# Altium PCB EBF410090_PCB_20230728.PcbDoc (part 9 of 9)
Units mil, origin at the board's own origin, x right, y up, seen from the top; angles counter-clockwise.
Board outline 5393.69 x 3858.26 mil, 6 copper layers (TOP, GND02, ART03, ART04, PWR05, BOTTOM), stack 47.2 mil thick; 570 components, 437 nets, 2015 pads, 1260 vias.
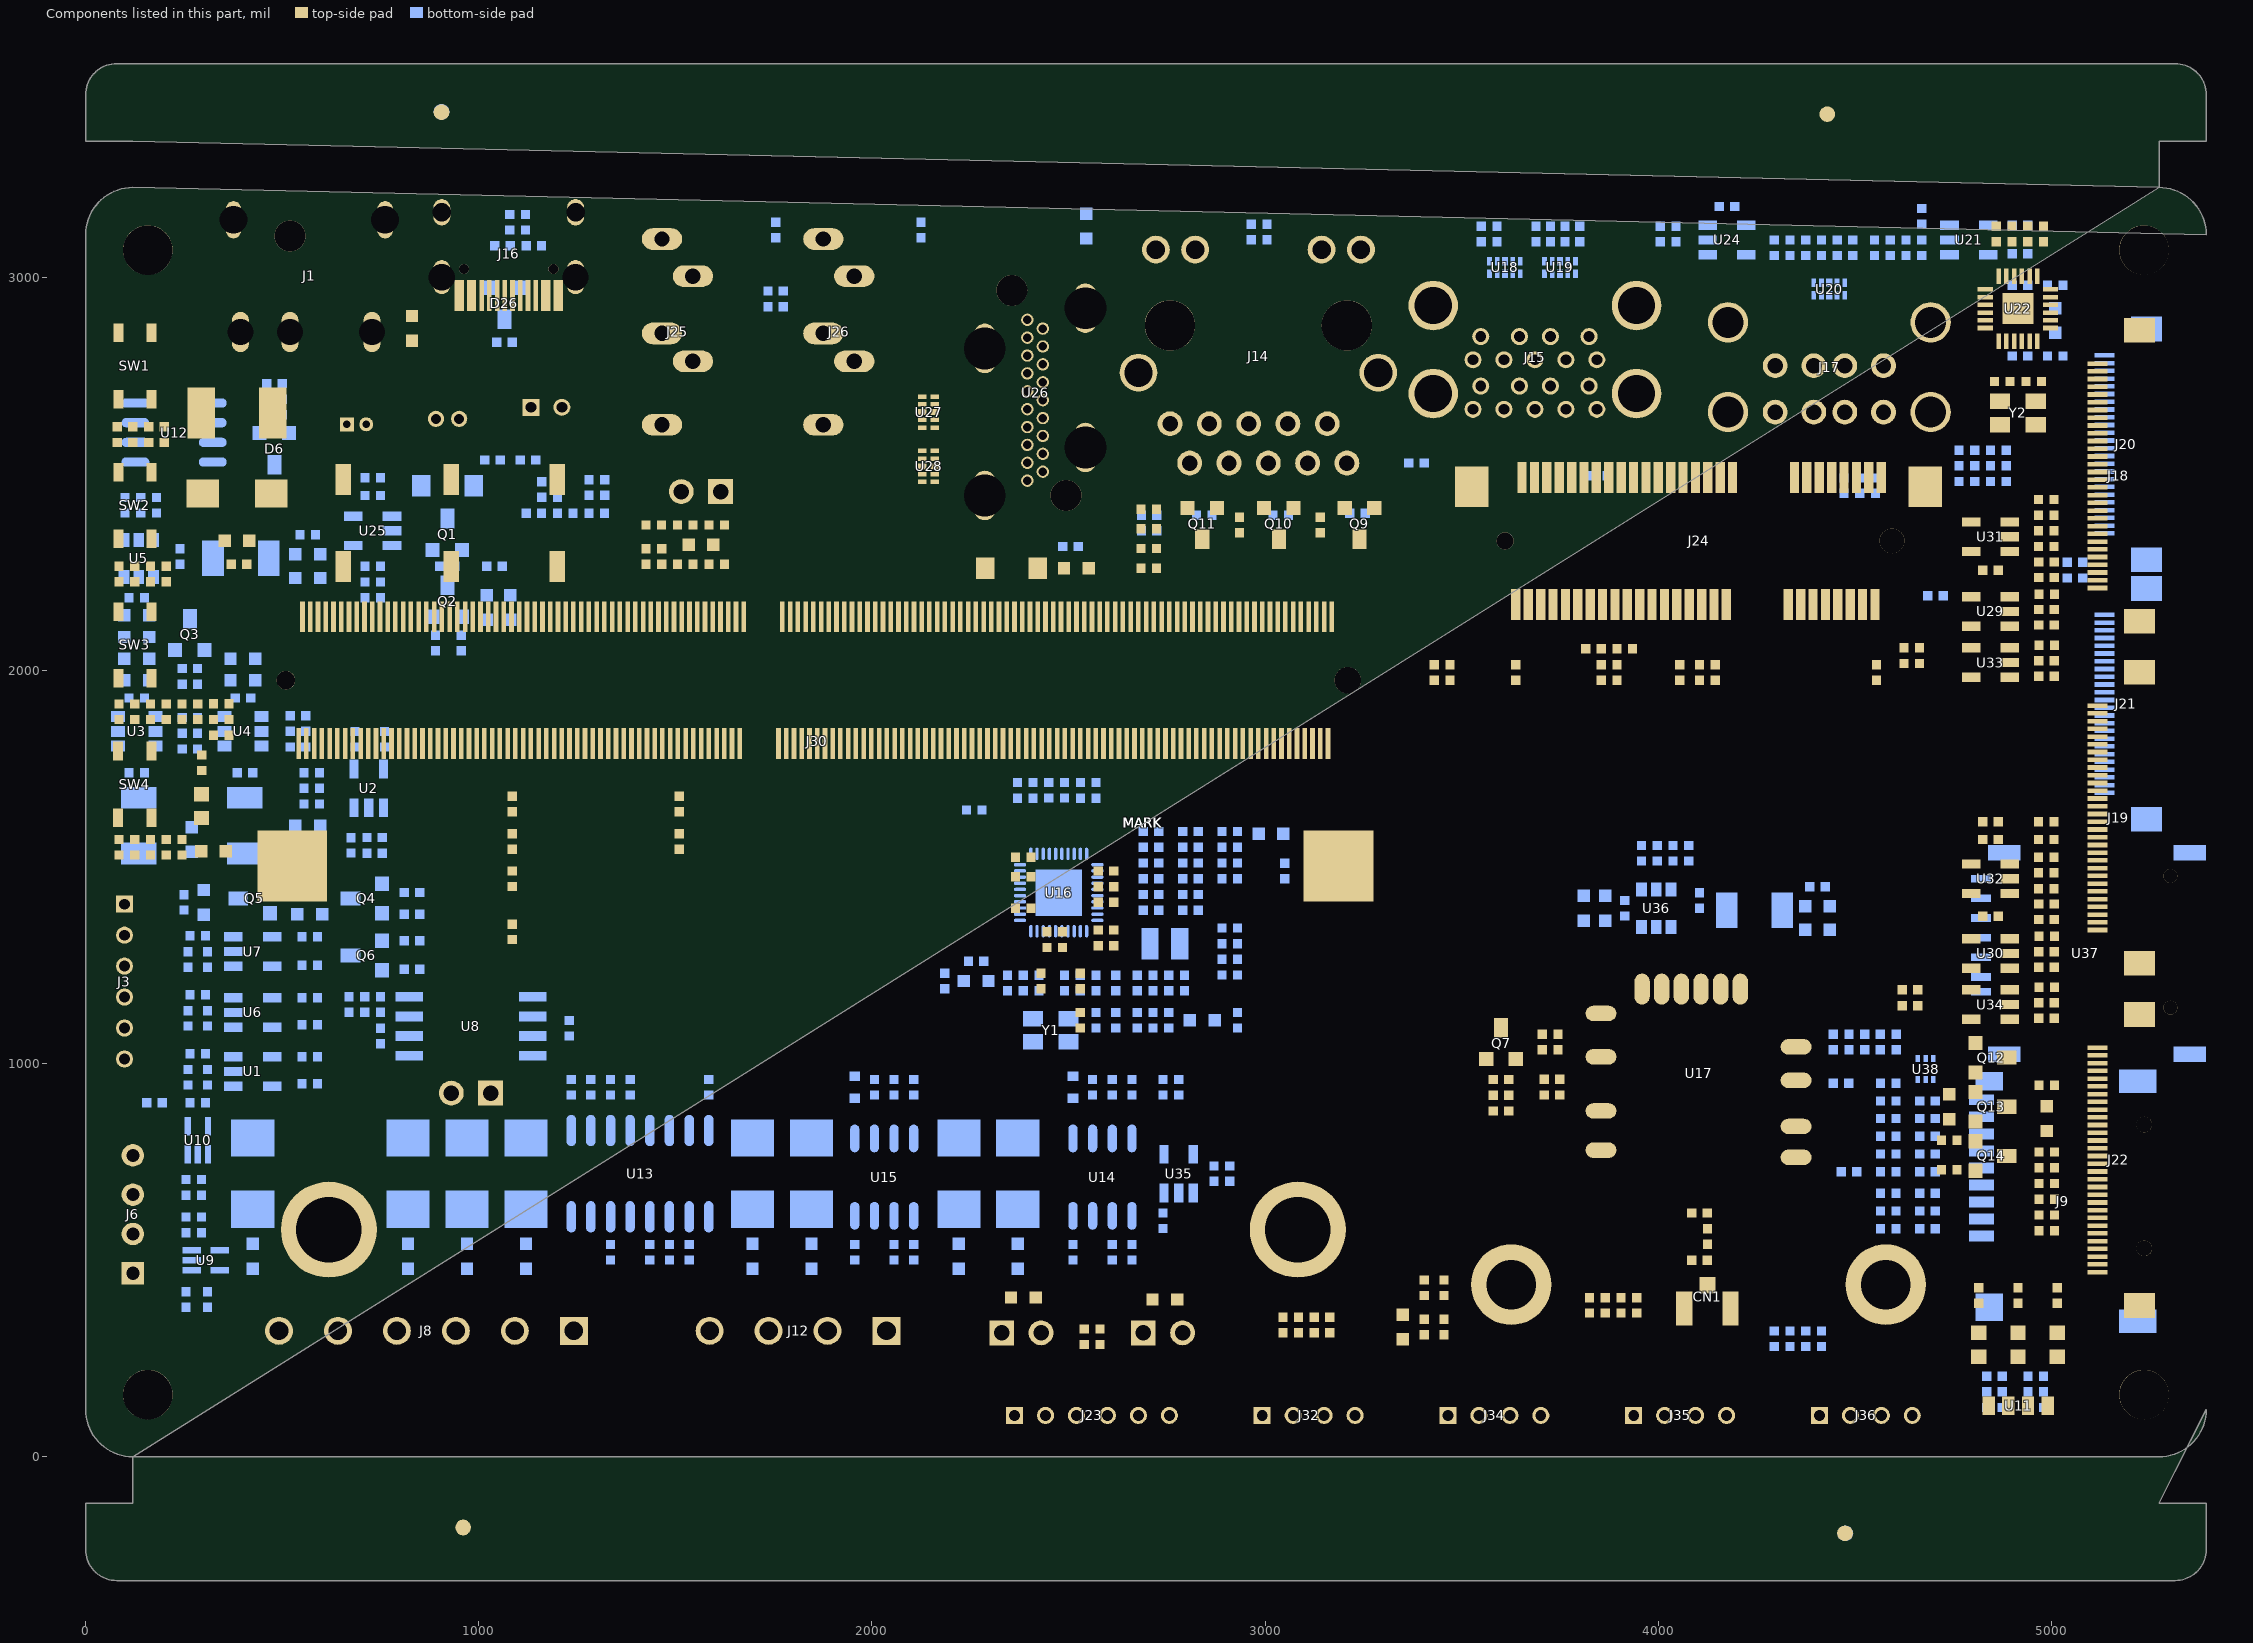
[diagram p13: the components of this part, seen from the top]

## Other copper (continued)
BOTTOM:
  region net GND: 896.3,2616 905.6,2625.33 890.99,2641.8 876.38,2625.33 885.68,2616 886.16,2615.56 886.68,2615.16 887.23,2614.81 887.81,2614.51 888.42,2614.25 889.04,2614.06 889.68,2613.92 890.33,2613.83 890.98,2613.8 891.64,2613.83 892.29,2613.91 892.92,2614.05 893.55,2614.25 894.15,2614.5 894.73,2614.8 895.29,2615.15 895.81,2615.55 896.29,2615.99 896.3,2616
  region net B_DP2: 4424.11,2806.64 4395.73,2806.64 4395.18,2774.6 4427.22,2775.15 4427.22,2803.53 4427.21,2803.8 4427.17,2804.07 4427.11,2804.33 4427.03,2804.59 4426.93,2804.84 4426.8,2805.09 4426.66,2805.31 4426.49,2805.53 4426.31,2805.73 4426.11,2805.91 4425.89,2806.08 4425.66,2806.22 4425.42,2806.35 4425.17,2806.45 4424.91,2806.53 4424.65,2806.59 4424.38,2806.63 4424.11,2806.64
  region net N15603170: 3245.6,2534.59 3230.39,2549.78 3205.63,2527.52 3230.39,2505.26 3245.6,2520.45 3246.19,2521.09 3246.72,2521.78 3247.19,2522.52 3247.59,2523.29 3247.93,2524.1 3248.19,2524.93 3248.38,2525.78 3248.49,2526.65 3248.53,2527.52 3248.49,2528.39 3248.38,2529.26 3248.19,2530.11 3247.93,2530.94 3247.59,2531.75 3247.19,2532.52 3246.72,2533.26 3246.19,2533.95 3245.6,2534.59
  region net VCC5V0_USB20_HOST: 4565.83,2812.62 4550.64,2797.41 4572.9,2772.65 4595.16,2797.41 4579.97,2812.62 4579.33,2813.21 4578.64,2813.74 4577.9,2814.21 4577.13,2814.61 4576.32,2814.95 4575.49,2815.21 4574.64,2815.4 4573.77,2815.51 4572.9,2815.55 4572.03,2815.51 4571.16,2815.4 4570.31,2815.21 4569.48,2814.95 4568.67,2814.61 4567.9,2814.21 4567.16,2813.74 4566.47,2813.21 4565.83,2812.62
  region net EDP_TP_RESET: 2538.78,126.66 2520.2,126.65 2519.66,104.47 2541.85,105.01 2541.86,123.58 2541.85,123.85 2541.81,124.11 2541.76,124.38 2541.67,124.63 2541.57,124.88 2541.45,125.12 2541.3,125.35 2541.14,125.56 2540.96,125.76 2540.76,125.94 2540.55,126.1 2540.32,126.25 2540.08,126.37 2539.83,126.47 2539.58,126.56 2539.31,126.61 2539.05,126.65 2538.78,126.66
  region net N18341998: 3100.72,3063.37 3118.7,3045.39 3146.26,3070.44 3118.7,3095.49 3100.72,3077.51 3100.13,3076.87 3099.6,3076.18 3099.13,3075.44 3098.73,3074.67 3098.39,3073.86 3098.13,3073.03 3097.94,3072.18 3097.83,3071.31 3097.79,3070.44 3097.83,3069.57 3097.94,3068.7 3098.13,3067.85 3098.39,3067.02 3098.73,3066.21 3099.13,3065.44 3099.6,3064.7 3100.13,3064.01 3100.72,3063.37
  region net VCC5V0_USB20_HOST: 4579.97,2737.68 4595.16,2752.89 4572.9,2777.65 4550.64,2752.89 4565.83,2737.68 4566.47,2737.09 4567.16,2736.56 4567.9,2736.09 4568.67,2735.69 4569.48,2735.35 4570.31,2735.09 4571.16,2734.9 4572.03,2734.79 4572.9,2734.75 4573.77,2734.79 4574.64,2734.9 4575.49,2735.09 4576.32,2735.35 4577.13,2735.69 4577.9,2736.09 4578.64,2736.56 4579.33,2737.09 4579.97,2737.68
  region net N15852295: 1167.28,2648.57 1154.14,2690.94 1131.47,2670.02 1110.82,2647.64 1162.37,2642.64 1162.81,2642.66 1163.24,2642.72 1163.66,2642.81 1164.08,2642.94 1164.48,2643.11 1164.87,2643.31 1165.24,2643.54 1165.58,2643.81 1165.91,2644.1 1166.2,2644.43 1166.47,2644.77 1166.7,2645.14 1166.9,2645.53 1167.07,2645.93 1167.2,2646.35 1167.29,2646.77 1167.35,2647.2 1167.37,2647.64 1167.35,2648.08 1167.29,2648.51 1167.28,2648.57
  region net N17975561: 661.06,2660.41 646.66,2643.7 664.37,2624.48 682.08,2643.7 667.68,2660.41 667.23,2660.68 666.76,2660.9 666.27,2661.09 665.77,2661.24 665.25,2661.33 664.73,2661.39 664.21,2661.4 663.69,2661.36 663.17,2661.28 662.66,2661.15 662.17,2660.98 661.69,2660.77 661.23,2660.51 661.06,2660.41
  region net EDP_TP_INT: 2460.04,126.66 2441.46,126.65 2440.92,104.47 2463.11,105.01 2463.12,123.58 2463.11,123.85 2463.07,124.11 2463.02,124.38 2462.93,124.63 2462.83,124.88 2462.71,125.12 2462.56,125.35 2462.4,125.56 2462.22,125.76 2462.02,125.94 2461.81,126.1 2461.58,126.25 2461.34,126.37 2461.09,126.47 2460.84,126.56 2460.57,126.61 2460.31,126.65 2460.04,126.66
  region net B_DP3: 4424.11,2688.54 4395.73,2688.52 4395.18,2656.49 4427.22,2657.04 4427.22,2685.42 4427.21,2685.69 4427.17,2685.96 4427.11,2686.23 4427.03,2686.49 4426.93,2686.74 4426.8,2686.98 4426.66,2687.21 4426.49,2687.43 4426.31,2687.63 4426.11,2687.81 4425.89,2687.98 4425.66,2688.12 4425.42,2688.25 4425.17,2688.35 4424.91,2688.43 4424.64,2688.49 4424.37,2688.53 4424.11,2688.54
  region net N17702199: 1633.51,323.71 1611.98,345.22 1585.68,320.17 1611.98,295.12 1633.51,316.63 1633.81,316.95 1634.07,317.3 1634.31,317.67 1634.51,318.05 1634.68,318.46 1634.81,318.87 1634.9,319.3 1634.96,319.73 1634.98,320.17 1634.96,320.61 1634.9,321.04 1634.81,321.47 1634.68,321.88 1634.51,322.29 1634.31,322.68 1634.07,323.04 1633.81,323.39 1633.51,323.71
  region net N18495175: 4486.52,133.46 4473.4,120.32 4488.7,104.24 4504,120.32 4490.88,133.46 4490.68,133.64 4490.47,133.8 4490.24,133.95 4490,134.07 4489.75,134.17 4489.5,134.26 4489.23,134.31 4488.97,134.35 4488.7,134.36 4488.43,134.35 4488.17,134.31 4487.9,134.26 4487.65,134.17 4487.4,134.07 4487.16,133.95 4486.93,133.8 4486.72,133.64 4486.52,133.46
  region net N17731599: 456.23,350.6 456.24,320.17 492.54,319.29 491.66,355.59 461.23,355.6 460.79,355.58 460.36,355.52 459.94,355.43 459.52,355.3 459.12,355.13 458.73,354.93 458.36,354.7 458.02,354.43 457.69,354.14 457.4,353.81 457.13,353.47 456.9,353.1 456.7,352.71 456.53,352.31 456.4,351.89 456.31,351.47 456.25,351.04 456.23,350.6
  region net N18495177: 4565.26,133.46 4552.14,120.32 4567.44,104.24 4582.74,120.32 4569.62,133.46 4569.42,133.64 4569.21,133.8 4568.98,133.95 4568.74,134.07 4568.49,134.17 4568.24,134.26 4567.97,134.31 4567.71,134.35 4567.44,134.36 4567.17,134.35 4566.91,134.31 4566.64,134.26 4566.39,134.17 4566.14,134.07 4565.9,133.95 4565.67,133.8 4565.46,133.64 4565.26,133.46
  region net N15852481: 1194.57,2647.64 1211.22,2647.65 1212.1,2670.17 1189.58,2669.29 1189.57,2652.64 1189.59,2652.2 1189.65,2651.77 1189.74,2651.35 1189.87,2650.93 1190.04,2650.53 1190.24,2650.14 1190.47,2649.77 1190.74,2649.43 1191.03,2649.1 1191.36,2648.81 1191.7,2648.54 1192.07,2648.31 1192.46,2648.11 1192.86,2647.94 1193.28,2647.81 1193.7,2647.72 1194.13,2647.66 1194.57,2647.64
  region net B_DM2: 4442.98,2803.53 4442.98,2775.15 4475.02,2774.6 4474.47,2806.64 4446.09,2806.64 4445.82,2806.63 4445.55,2806.59 4445.29,2806.53 4445.03,2806.45 4444.78,2806.35 4444.53,2806.22 4444.31,2806.08 4444.09,2805.91 4443.89,2805.73 4443.71,2805.53 4443.54,2805.31 4443.4,2805.09 4443.27,2804.84 4443.17,2804.59 4443.09,2804.33 4443.03,2804.07 4442.99,2803.8 4442.98,2803.53
  pour cut-out: 1103,2879 1035,2879 1035,2998 1103,2998 1103,2879
  region net B_DM3: 4442.98,2685.42 4442.98,2657.04 4475.02,2656.49 4474.47,2688.52 4446.09,2688.54 4445.82,2688.53 4445.55,2688.49 4445.29,2688.43 4445.03,2688.35 4444.78,2688.25 4444.53,2688.12 4444.31,2687.98 4444.09,2687.81 4443.89,2687.63 4443.71,2687.43 4443.54,2687.21 4443.4,2686.99 4443.27,2686.74 4443.17,2686.49 4443.09,2686.23 4443.03,2685.97 4442.99,2685.7 4442.98,2685.43 4442.98,2685.42
  region net 5V_OUT: 126.54,1250.62 114.05,1263.11 96.88,1248.01 112.62,1231.38 125.11,1238.9 125.66,1239.26 126.17,1239.67 126.64,1240.12 127.08,1240.61 127.46,1241.13 127.8,1241.69 128.1,1242.28 128.33,1242.89 128.52,1243.52 128.65,1244.16 128.72,1244.81 128.74,1245.46 128.7,1246.11 128.6,1246.76 128.45,1247.4 128.24,1248.02 127.98,1248.62 127.66,1249.19 127.3,1249.74 126.89,1250.25 126.54,1250.62
  region net N18348384: 970,353.51 943.76,353.5 940.78,319.29 974.99,322.27 975,348.51 974.98,348.95 974.92,349.38 974.83,349.8 974.7,350.22 974.53,350.62 974.33,351.01 974.1,351.38 973.83,351.72 973.54,352.05 973.21,352.34 972.87,352.61 972.5,352.84 972.11,353.04 971.71,353.21 971.29,353.34 970.87,353.43 970.44,353.49 970,353.51
  region net DBG_TXD: 145.46,595.08 120,595.07 119.46,566 148.53,566.54 148.54,592 148.53,592.27 148.49,592.53 148.44,592.8 148.35,593.05 148.25,593.3 148.13,593.54 147.98,593.77 147.82,593.98 147.64,594.18 147.44,594.36 147.23,594.52 147,594.67 146.76,594.79 146.51,594.89 146.26,594.98 145.99,595.03 145.73,595.07 145.46,595.08
  region net N17731608: 820,353.51 793.76,353.5 790.78,319.29 824.99,322.27 825,348.51 824.98,348.95 824.92,349.38 824.83,349.8 824.7,350.22 824.53,350.62 824.33,351.01 824.1,351.38 823.83,351.72 823.54,352.05 823.21,352.34 822.87,352.61 822.5,352.84 822.11,353.04 821.71,353.21 821.29,353.34 820.87,353.43 820.44,353.49 820,353.51
  region net N17702222: 1933.51,323.71 1911.98,345.22 1885.68,320.17 1911.98,295.12 1933.51,316.63 1933.81,316.95 1934.07,317.3 1934.31,317.67 1934.51,318.05 1934.68,318.46 1934.81,318.87 1934.9,319.3 1934.96,319.73 1934.98,320.17 1934.96,320.61 1934.9,321.04 1934.81,321.47 1934.68,321.88 1934.51,322.29 1934.31,322.68 1934.07,323.04 1933.81,323.39 1933.51,323.71
  region net 3V3_OUT: 126.13,1102.43 111.12,1107.43 96.9,1089.95 114.05,1075.01 129.06,1090.02 129.51,1090.5 129.9,1091.02 130.26,1091.57 130.56,1092.15 130.81,1092.75 131,1093.38 131.15,1094.02 131.23,1094.67 131.26,1095.32 131.23,1095.97 131.15,1096.62 131,1097.26 130.81,1097.89 130.56,1098.49 130.26,1099.07 129.9,1099.62 129.51,1100.14 129.06,1100.62 128.58,1101.07 128.06,1101.46 127.51,1101.82 126.93,1102.12 126.33,1102.37 126.13,1102.43
  region net FSPI_D0: 887.64,922.82 907.74,902.74 930.77,925 907.74,947.26 887.64,927.18 887.46,926.98 887.3,926.77 887.15,926.54 887.03,926.3 886.93,926.05 886.84,925.8 886.79,925.53 886.75,925.27 886.74,925 886.75,924.73 886.79,924.47 886.84,924.2 886.93,923.95 887.03,923.7 887.15,923.46 887.3,923.23 887.46,923.02 887.64,922.82
  region net N17750554: 955.36,2616 964.66,2625.33 950.05,2641.8 935.44,2625.33 944.74,2616 945.22,2615.56 945.74,2615.16 946.29,2614.81 946.87,2614.51 947.48,2614.25 948.1,2614.06 948.74,2613.92 949.39,2613.83 950.04,2613.8 950.7,2613.83 951.35,2613.91 951.98,2614.05 952.61,2614.25 953.21,2614.5 953.79,2614.8 954.35,2615.15 954.87,2615.55 955.35,2615.99 955.36,2616
  region net N17702194: 1690.35,316.63 1711.88,295.12 1738.18,320.17 1711.88,345.22 1690.35,323.71 1690.05,323.39 1689.79,323.04 1689.55,322.68 1689.35,322.29 1689.18,321.88 1689.05,321.47 1688.96,321.04 1688.9,320.61 1688.88,320.17 1688.9,319.73 1688.96,319.3 1689.05,318.87 1689.18,318.46 1689.35,318.05 1689.55,317.67 1689.79,317.3 1690.05,316.95 1690.35,316.63
  region net GND: 1056.22,349.6 1056.23,320.17 1092.72,319.11 1091.66,355.59 1062.22,355.6 1061.7,355.58 1061.18,355.51 1060.67,355.4 1060.17,355.24 1059.68,355.04 1059.22,354.8 1058.78,354.51 1058.36,354.2 1057.98,353.84 1057.62,353.46 1057.31,353.04 1057.02,352.6 1056.78,352.14 1056.58,351.65 1056.42,351.15 1056.31,350.64 1056.24,350.12 1056.22,349.6
  region net DBG_RXD: 159.73,667.18 140.18,686.71 119.23,666.57 139.99,646.18 159.54,662.64 159.54,662.65 159.73,662.83 159.91,663.03 160.08,663.24 160.22,663.47 160.34,663.71 160.45,663.95 160.53,664.21 160.58,664.47 160.62,664.74 160.63,665.01 160.62,665.28 160.58,665.54 160.52,665.8 160.44,666.06 160.34,666.31 160.21,666.55 160.07,666.77 159.9,666.99 159.73,667.18
  region net VCC5V0_USB20_HOST: 4565.83,2694.51 4550.64,2679.3 4572.9,2654.54 4595.16,2679.3 4579.97,2694.51 4579.33,2695.1 4578.64,2695.63 4577.9,2696.1 4577.13,2696.5 4576.32,2696.84 4575.49,2697.1 4574.64,2697.29 4573.77,2697.4 4572.9,2697.44 4572.03,2697.4 4571.16,2697.29 4570.31,2697.1 4569.48,2696.84 4568.67,2696.5 4567.9,2696.1 4567.16,2695.63 4566.47,2695.1 4565.83,2694.51
  region net N17702231: 1985.59,317.53 2001.51,301.43 2038.18,320.17 2001.51,338.91 1985.59,322.81 1985.38,322.43 1985.2,322.03 1985.06,321.62 1984.95,321.2 1984.88,320.77 1984.84,320.34 1984.85,319.9 1984.89,319.47 1984.97,319.04 1985.09,318.62 1985.24,318.21 1985.43,317.82 1985.59,317.53
  region net GND: 1034.86,867.26 1061.5,893.5 1030,927.5 998.5,893.5 1025.14,867.26 1025.92,866.87 1026.73,866.55 1027.57,866.3 1028.42,866.13 1029.29,866.03 1030.16,866 1031.03,866.05 1031.89,866.18 1032.74,866.38 1033.57,866.66 1034.37,867.01 1034.86,867.26
  region net N17697466: 2865.14,3077.51 2847.16,3095.49 2819.6,3070.44 2847.16,3045.39 2865.14,3063.37 2865.73,3064.01 2866.26,3064.7 2866.73,3065.44 2867.13,3066.21 2867.47,3067.02 2867.73,3067.85 2867.92,3068.7 2868.03,3069.57 2868.07,3070.44 2868.03,3071.31 2867.92,3072.18 2867.73,3073.03 2867.47,3073.86 2867.13,3074.67 2866.73,3075.44 2866.26,3076.18 2865.73,3076.87 2865.14,3077.51

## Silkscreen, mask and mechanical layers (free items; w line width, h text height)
OUTLINE:
  lines w1: 0,3108.34 cw(c120,3108.34) 120,3228.34 5273.69,3228.34 cw(c5273.69,3108.34) 5393.69,3108.34 ; 120,0 5273.69,0
  lines w6: 0,3108.34 0,120 ccw(c120,120) 120,0 ; 5393.69,120 cw(c5273.69,120) 5273.69,0 ; 120,0 120,-118.11 0,-118.11 0,-236.22 ccw(c78.74,-236.22) 78.74,-314.96 5314.95,-314.96 ccw(c5314.95,-236.22) 5393.69,-236.22 5393.69,-118.11 5273.69,-118.11 5273.69,0 ; 120,0 5273.69,0 ; 0,3346.45 0,3464.56 cw(c78.74,3464.56) 78.74,3543.3 5314.95,3543.3 cw(c5314.95,3464.56) 5393.69,3464.56 5393.69,3346.45 5273.69,3346.45 5273.69,3228.34 120,3228.34 120,3346.45 0,3346.45
NCLEGEND-1-6:
  circle w1: c7250.5,4491 r36.02
  lines w1: 6801,-634 11637,-634 ; 6801,-384 11637,-384 ; 6801,-134 11637,-134 ; 6801,116 11637,116 ; 6801,366 11637,366 ; 6801,616 11637,616 ; 6801,866 11637,866 ; 6801,1116 11637,1116 ; 6801,1366 11637,1366 ; 6801,1616 11637,1616 ; 6801,1866 11637,1866 ; 6801,2116 11637,2116 ; 6801,2366 11637,2366 ; 6801,2616 11637,2616 ; 6801,2866 11637,2866 ; 6801,3116 11637,3116 ; 6801,3366 11637,3366 ; 6801,3616 11637,3616 ; 6801,3866 11637,3866 ; 6801,4116 11637,4116 ; 6801,4366 11637,4366 ; 6801,4616 11637,4616 ; 6801,4866 11637,4866 ; 6801,5116 11637,5116 ; 6801,5366 11637,5366 ; 6801,5616 11637,5616 ; 6801,5866 11637,5866 ; 6801,6116 11637,6116 ; 6801,6366 11637,6366 ; 6801,6616 11637,6616 ; 6801,6866 11637,6866 ; 6801,7116 11637,7116 ; 6801,7366 11637,7366 ; 6801,7616 11637,7616 ; 7244.5,6991 7256.5,6991 ; 7250.5,6985 7250.5,6997 ; 7700,-884 7700,7366 ; 9591,-884 9591,7366 ; 10862,-884 10862,7366 ; 6801,-884 6801,7866 11637,7866 11637,-884 6801,-884 ; 7215.06,-794.43 ccw(c7215.06,-759) 7215.06,-723.57 7285.94,-723.57 ccw(c7285.94,-759) 7285.94,-794.43 7215.06,-794.43 ; 7220.67,5991 7229.41,5969.91 7250.5,5961.17 7271.59,5969.91 7280.33,5991 7271.59,6012.09 7250.5,6020.83 7229.41,6012.09 7220.67,5991 ; 7220.97,5236.08 ccw(c7250.5,5236.08) 7280.03,5236.08 7280.03,5245.92 ccw(c7250.5,5245.92) 7220.97,5245.92 7220.97,5236.08 ; 7222.9,-24.7 ccw(c7222.9,-9) 7222.9,6.7 7278.1,6.7 ccw(c7278.1,-9) 7278.1,-24.7 7222.9,-24.7 ; 7226.9,471.3 ccw(c7226.9,491) 7226.9,510.7 7274.1,510.7 ccw(c7274.1,491) 7274.1,471.3 7226.9,471.3 ; 7226.88,4723.28 7226.88,4758.72 7274.12,4758.72 7274.12,4723.28 7226.88,4723.28 ; 7228.85,217.38 ccw(c7228.85,241) 7228.85,264.62 7272.15,264.62 ccw(c7272.15,241) 7272.15,217.38 7228.85,217.38 ; 7230.81,-298.37 ccw(c7230.81,-259) 7230.81,-219.63 7270.19,-219.63 ccw(c7270.19,-259) 7270.19,-298.37 7230.81,-298.37 ; 7230.81,4971.31 7250.5,5010.69 7270.19,4971.31 7230.81,4971.31 ; 7233.77,5741 7250.5,5757.73 7267.23,5741 7250.5,5724.27 7233.77,5741 ; 7237.7,6234.6 7250.5,6228.2 7263.3,6234.6 7263.3,6247.4 7250.5,6253.8 7237.7,6247.4 7237.7,6234.6 ; 7238.69,717.38 ccw(c7238.69,741) 7238.69,764.62 7262.31,764.62 ccw(c7262.31,741) 7262.31,717.38 7238.69,717.38 ; 7239.68,6491 7245.09,6480.18 7255.91,6480.18 7261.32,6491 7255.91,6501.82 7245.09,6501.82 7239.68,6491 ; 7240.65,6731.15 7260.35,6731.15 7260.35,6750.85 7240.65,6750.85 7240.65,6731.15 ; 7245.58,5461.47 ccw(c7245.58,5491) 7245.58,5520.53 7255.42,5520.53 ccw(c7255.42,5491) 7255.42,5461.47 7245.58,5461.47 ; 7250.5,-603.49 cw(c7250.5,-509) 7250.5,-414.51 cw(c7250.5,-509) 7250.5,-603.49 ; 7250.5,963.44 cw(c7250.5,991) 7250.5,1018.56 cw(c7250.5,991) 7250.5,963.44
  text "DRILL CHART: TOP to BOTTOM" at 7919,7678.5 h125
  text "ALL UNITS ARE IN MILS" at 8169,7428.5 h125
  text "FIGURE" at 6950.5,7178.5 h125
  text "SIZE" at 8445.5,7178.5 h125
  text "PLATED" at 9926.5,7178.5 h125
  text "QTY" at 11099.5,7178.5 h125
  text "12.0" at 8445.5,6928.5 h125
  text "PLATED" at 9926.5,6928.5 h125
  text "1260" at 11049.5,6928.5 h125
  text "19.69" at 8395.5,6678.5 h125
  text "PLATED" at 9926.5,6678.5 h125
  text "2" at 11199.5,6678.5 h125
  text "21.65" at 8395.5,6428.5 h125
  text "PLATED" at 9926.5,6428.5 h125
  text "19" at 11149.5,6428.5 h125
  text "25.59" at 8395.5,6178.5 h125
  text "PLATED" at 9926.5,6178.5 h125
  text "2" at 11199.5,6178.5 h125
  text "27.56" at 8395.5,5928.5 h125
  text "PLATED" at 9926.5,5928.5 h125
  text "30" at 11149.5,5928.5 h125
  text "33.46" at 8395.5,5678.5 h125
  text "PLATED" at 9926.5,5678.5 h125
  text "4" at 11199.5,5678.5 h125
  text "39.37" at 8395.5,5428.5 h125
  text "PLATED" at 9926.5,5428.5 h125
  text "14" at 11149.5,5428.5 h125
  text "39.37" at 8395.5,5178.5 h125
  text "PLATED" at 9926.5,5178.5 h125
  text "4" at 11199.5,5178.5 h125
  text "39.37" at 8395.5,4928.5 h125
  text "PLATED" at 9926.5,4928.5 h125
  text "8" at 11199.5,4928.5 h125
  text "47.24" at 8395.5,4678.5 h125
  text "PLATED" at 9926.5,4678.5 h125
  text "14" at 11149.5,4678.5 h125
  text "72.05" at 8395.5,4428.5 h125
  text "PLATED" at 9926.5,4428.5 h125
  text "2" at 11199.5,4428.5 h125
  text "78.74" at 8395.5,4178.5 h125
  text "PLATED" at 9926.5,4178.5 h125
  text "4" at 11199.5,4178.5 h125
  text "125.98" at 8345.5,3928.5 h125
  text "PLATED" at 9926.5,3928.5 h125
  text "2" at 11199.5,3928.5 h125
  text "166.14" at 8345.5,3678.5 h125
  text "PLATED" at 9926.5,3678.5 h125
  text "2" at 11199.5,3678.5 h125
  text "25.59" at 8395.5,3428.5 h125
  text "NON-PLATED" at 9726.5,3428.5 h125
  text "2" at 11199.5,3428.5 h125
  text "35.43" at 8395.5,3178.5 h125
  text "NON-PLATED" at 9726.5,3178.5 h125
  text "2" at 11199.5,3178.5 h125
  text "40.0" at 8445.5,2928.5 h125
  text "NON-PLATED" at 9726.5,2928.5 h125
  text "2" at 11199.5,2928.5 h125
  text "43.31" at 8395.5,2678.5 h125
  text "NON-PLATED" at 9726.5,2678.5 h125
  text "1" at 11199.5,2678.5 h125
  text "47.24" at 8395.5,2428.5 h125
  text "NON-PLATED" at 9726.5,2428.5 h125
  text "1" at 11199.5,2428.5 h125
  text "62.99" at 8395.5,2178.5 h125
  text "NON-PLATED" at 9726.5,2178.5 h125
  text "1" at 11199.5,2178.5 h125
  text "66.93" at 8395.5,1928.5 h125
  text "NON-PLATED" at 9726.5,1928.5 h125
  text "1" at 11199.5,1928.5 h125
  text "78.7" at 8445.5,1678.5 h125
  text "NON-PLATED" at 9726.5,1678.5 h125
  text "3" at 11199.5,1678.5 h125
  text "125.98" at 8345.5,1428.5 h125
  text "NON-PLATED" at 9726.5,1428.5 h125
  text "4" at 11199.5,1428.5 h125
  text "127.95" at 8345.5,1178.5 h125
  text "NON-PLATED" at 9726.5,1178.5 h125
  text "2" at 11199.5,1178.5 h125
  text "27.56x27.56" at 8095.5,928.5 h125
  text "PLATED" at 9926.5,928.5 h125
  text "18" at 11149.5,928.5 h125
  text "47.24x23.62" at 8095.5,678.5 h125
  text "PLATED" at 9926.5,678.5 h125
  text "2" at 11199.5,678.5 h125
  text "66.9x19.7" at 8195.5,428.5 h125
  text "PLATED" at 9926.5,428.5 h125
  text "3" at 11199.5,428.5 h125
  text "66.93x23.62" at 8095.5,178.5 h125
  text "PLATED" at 9926.5,178.5 h125
  text "2" at 11199.5,178.5 h125
  text "70.9x15.7" at 8195.5,-71.5 h125
  text "PLATED" at 9926.5,-71.5 h125
  text "2" at 11199.5,-71.5 h125
  text "78.74x39.37" at 8095.5,-321.5 h125
  text "PLATED" at 9926.5,-321.5 h125
  text "10" at 11149.5,-321.5 h125
  text "94.49x94.49" at 8095.5,-571.5 h125
  text "PLATED" at 9926.5,-571.5 h125
  text "4" at 11199.5,-571.5 h125
  text "106.3x35.43" at 8095.5,-821.5 h125
  text "PLATED" at 9926.5,-821.5 h125
  text "4" at 11199.5,-821.5 h125
DRAWING_ORIGIN:
  lines w1: -25,0 25,0 ; 0,-25 0,25
Mechanical 255:
  lines w1: 1325,1740 ccw(c1335,1740) 1335,1730 1485,1730 ccw(c1485,1740) 1495,1740 1495,1810 ccw(c1485,1810) 1485,1820 1335,1820 ccw(c1335,1810) 1325,1810 1325,1740 ; 2275,1325 2395,1325 2395,1515 2275,1515 2275,1325 ; 2360,2535 2475,2535 2475,2905 2360,2905 2360,2535 ; 2450,1525 2575,1525 2575,1650 2450,1650 2450,1525 ; 3525,2625 3875,2625 3875,2900 3525,2900 3525,2625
